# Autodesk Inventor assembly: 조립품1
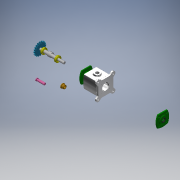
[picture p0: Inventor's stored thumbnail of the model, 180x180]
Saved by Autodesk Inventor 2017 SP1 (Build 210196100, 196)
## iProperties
Part Number: 조립품1
Material: 일반
Document SubType Name: Assembly
Designer: Administrator
Author: Administrator
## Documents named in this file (10)
- C:\Users\Administrator\Desktop\720106V1018\조립품1.iam
- C:\Users\Administrator\Desktop\720106V1018\본체.ipt
- C:\Users\Administrator\Desktop\720106V1018\편심축.ipt
- C:\Users\Administrator\Desktop\720106V1018\커버.ipt
- C:\Users\Administrator\Desktop\720106V1018\베어링 6203.ipt
- C:\Users\Administrator\Desktop\720106V1018\오일 실 17 x 30 x 8.ipt
- C:\Users\Administrator\Desktop\720106V1018\키 5 x 5.ipt
- C:\Users\Administrator\Desktop\720106V1018\스프로킷.ipt
- C:\Users\Administrator\Desktop\720106V1018\부시.ipt
- C:\Users\Administrator\Desktop\720106V1018\슬라이더.ipt
